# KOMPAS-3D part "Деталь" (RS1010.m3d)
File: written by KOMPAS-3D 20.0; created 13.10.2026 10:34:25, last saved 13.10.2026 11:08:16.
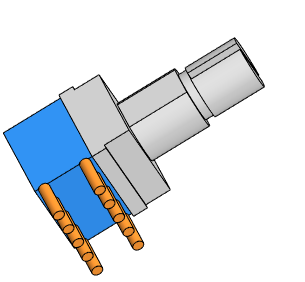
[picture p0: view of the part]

Document properties: Полное имя файла: D:\RicWork\Project-EPS32\box_compas\RS1010.m3d

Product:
- Part/product: Деталь
    Масса: 0.0129423

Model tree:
1. Эскиз:1
2. Элемент выдавливания:1
     Расстояние 1 = 11.7
3. Эскиз:2  (with: Элемент выдавливания:1)
4. Элемент выдавливания:2
     Расстояние 2 = 3
5. Эскиз:3  (with: Элемент выдавливания:1)
6. Элемент выдавливания:3
     Расстояние 2 = 7
7. Эскиз:5  (with: Элемент выдавливания:1)
8. Элемент выдавливания:6
     Расстояние 1 = 7
9. Эскиз:6  (with: Элемент выдавливания:6)
10. Элемент выдавливания:7
     Расстояние 1 = 1
11. Эскиз:7  (with: Элемент выдавливания:7)
12. Элемент выдавливания:9
     Расстояние 1 = 6
13. Эскиз:8  (with: Элемент выдавливания:3, Элемент выдавливания:2)
14. Элемент выдавливания:10
     Расстояние 1 = 4.5
15. Массив по сетке:2  (with: Элемент выдавливания:10, Эскиз:8)  (10 pattern instances)
     Шаг 1 = 2.54; Угол раствора = -90; Шаг 2 = 5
